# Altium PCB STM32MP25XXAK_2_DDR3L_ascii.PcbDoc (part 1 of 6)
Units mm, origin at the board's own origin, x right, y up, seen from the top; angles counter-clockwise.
Board outline 120 x 79.6 mm, 4 copper layers (Top Layer, Signal Layer 1, Signal Layer 2, Bottom Layer), stack 1.614 mm thick; 247 components, 155 nets, 1312 pads, 792 vias.
Unrouted connection lines stored in the file: 6.
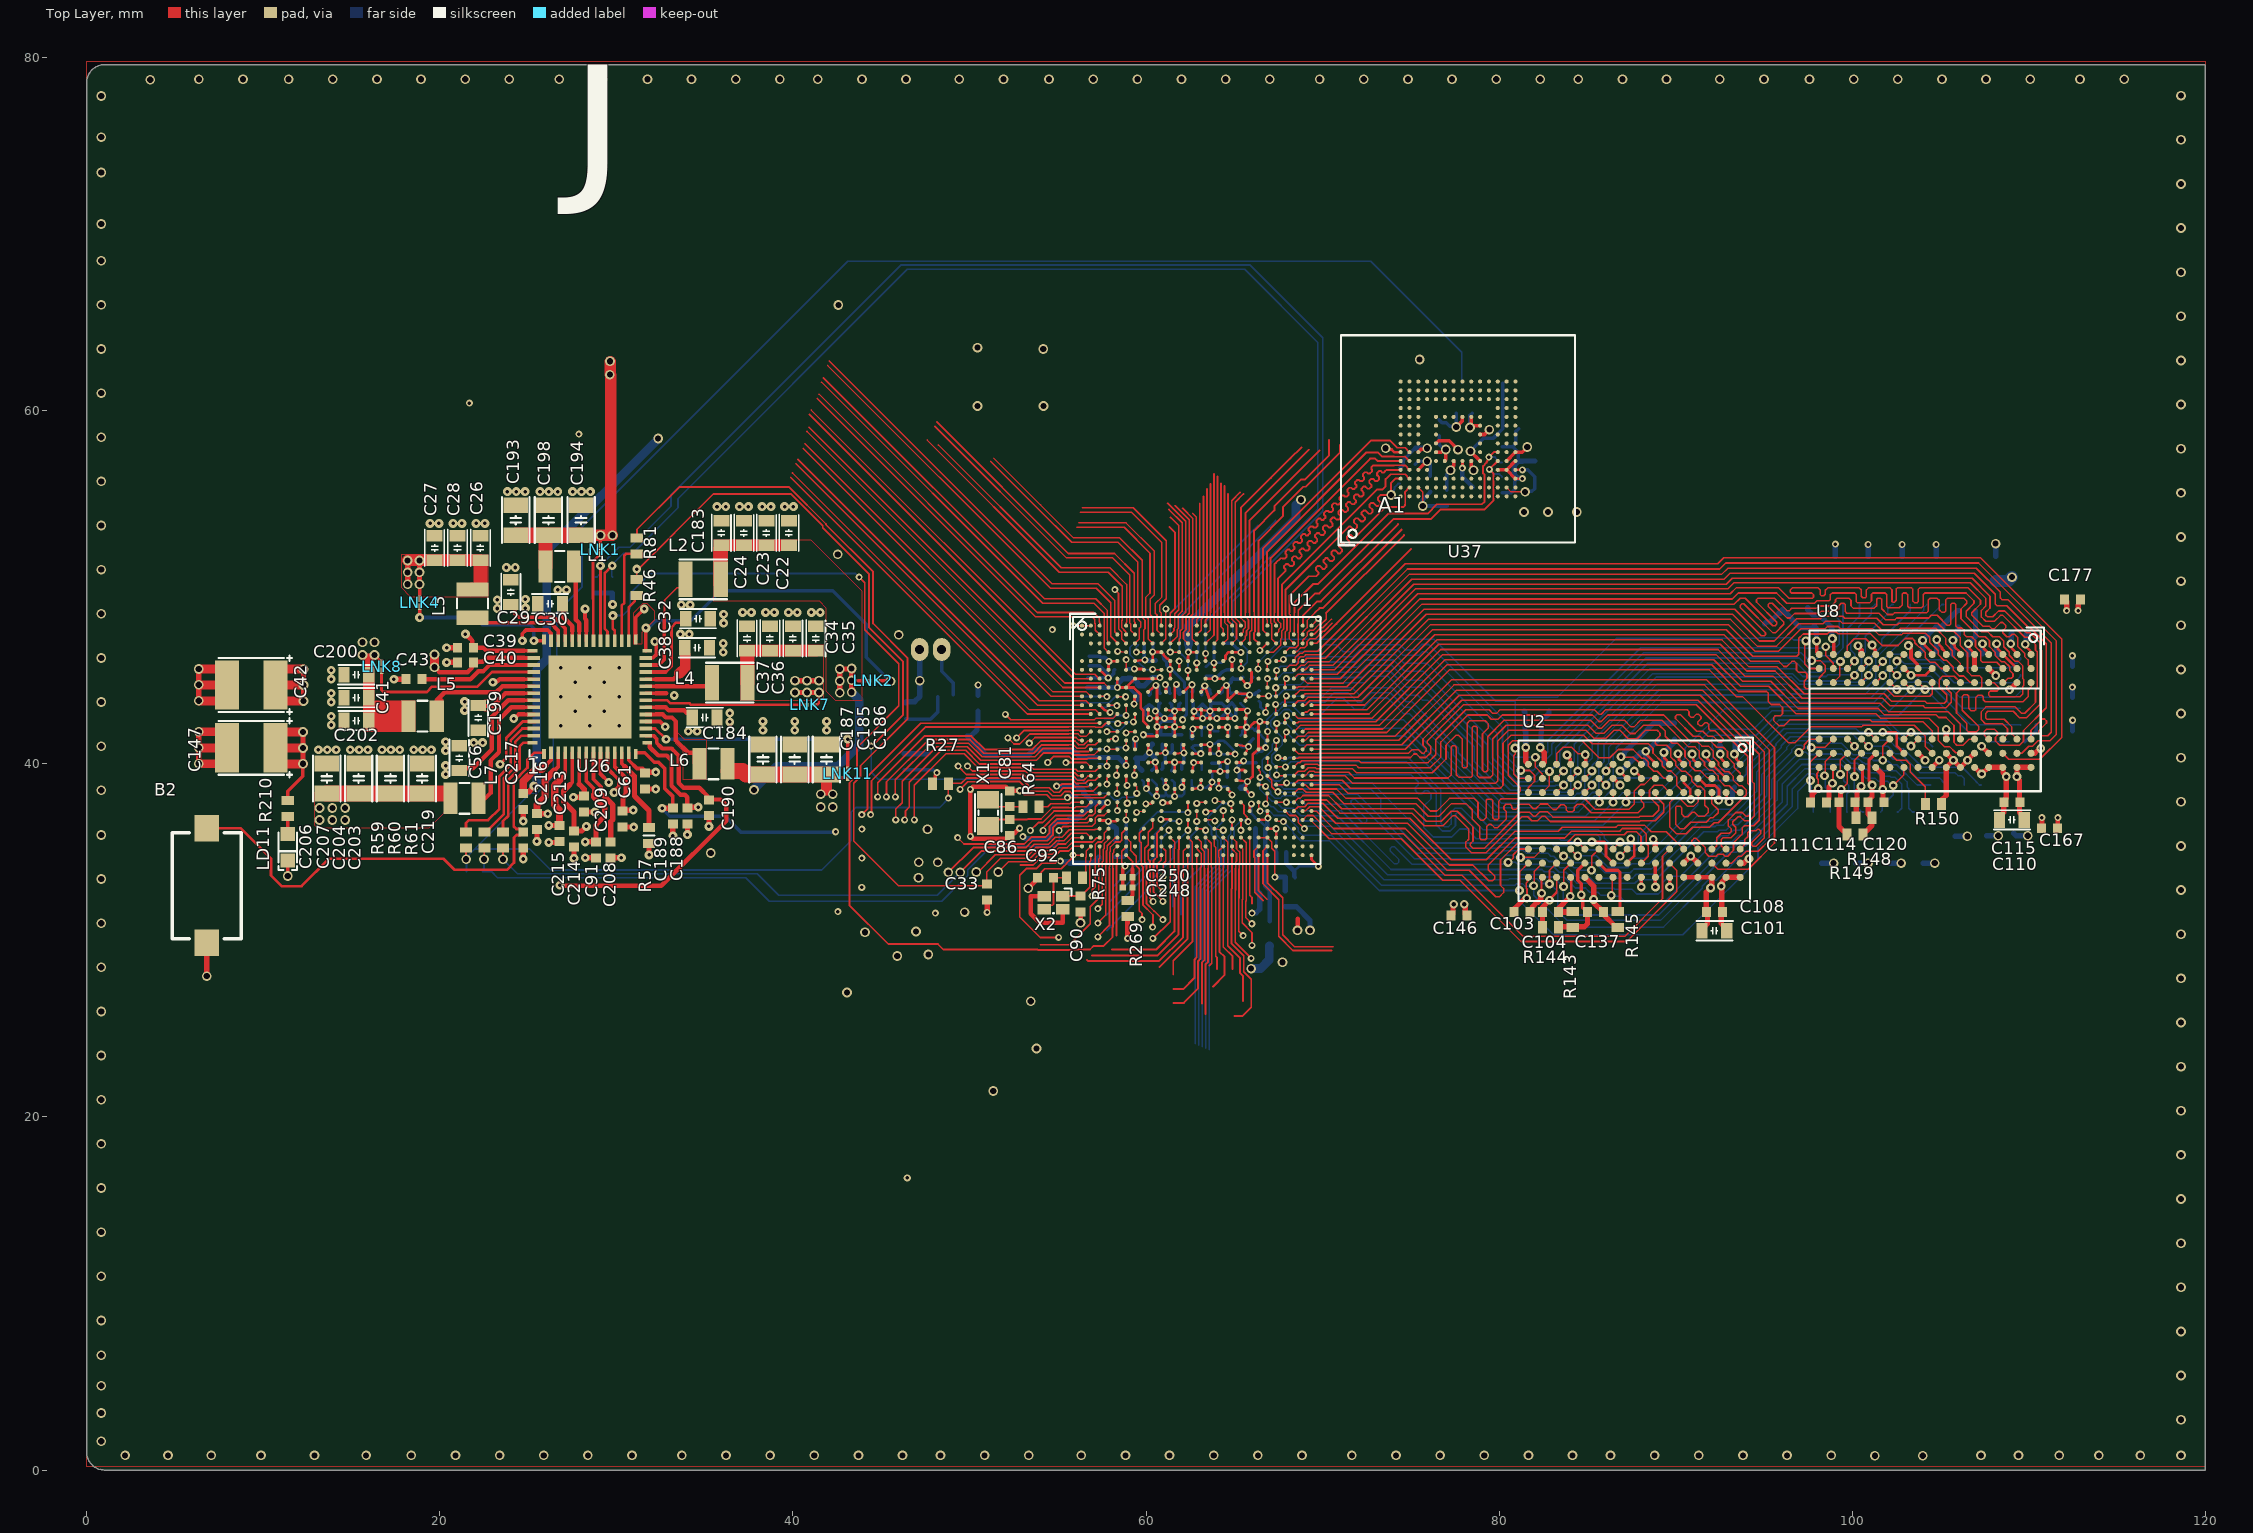
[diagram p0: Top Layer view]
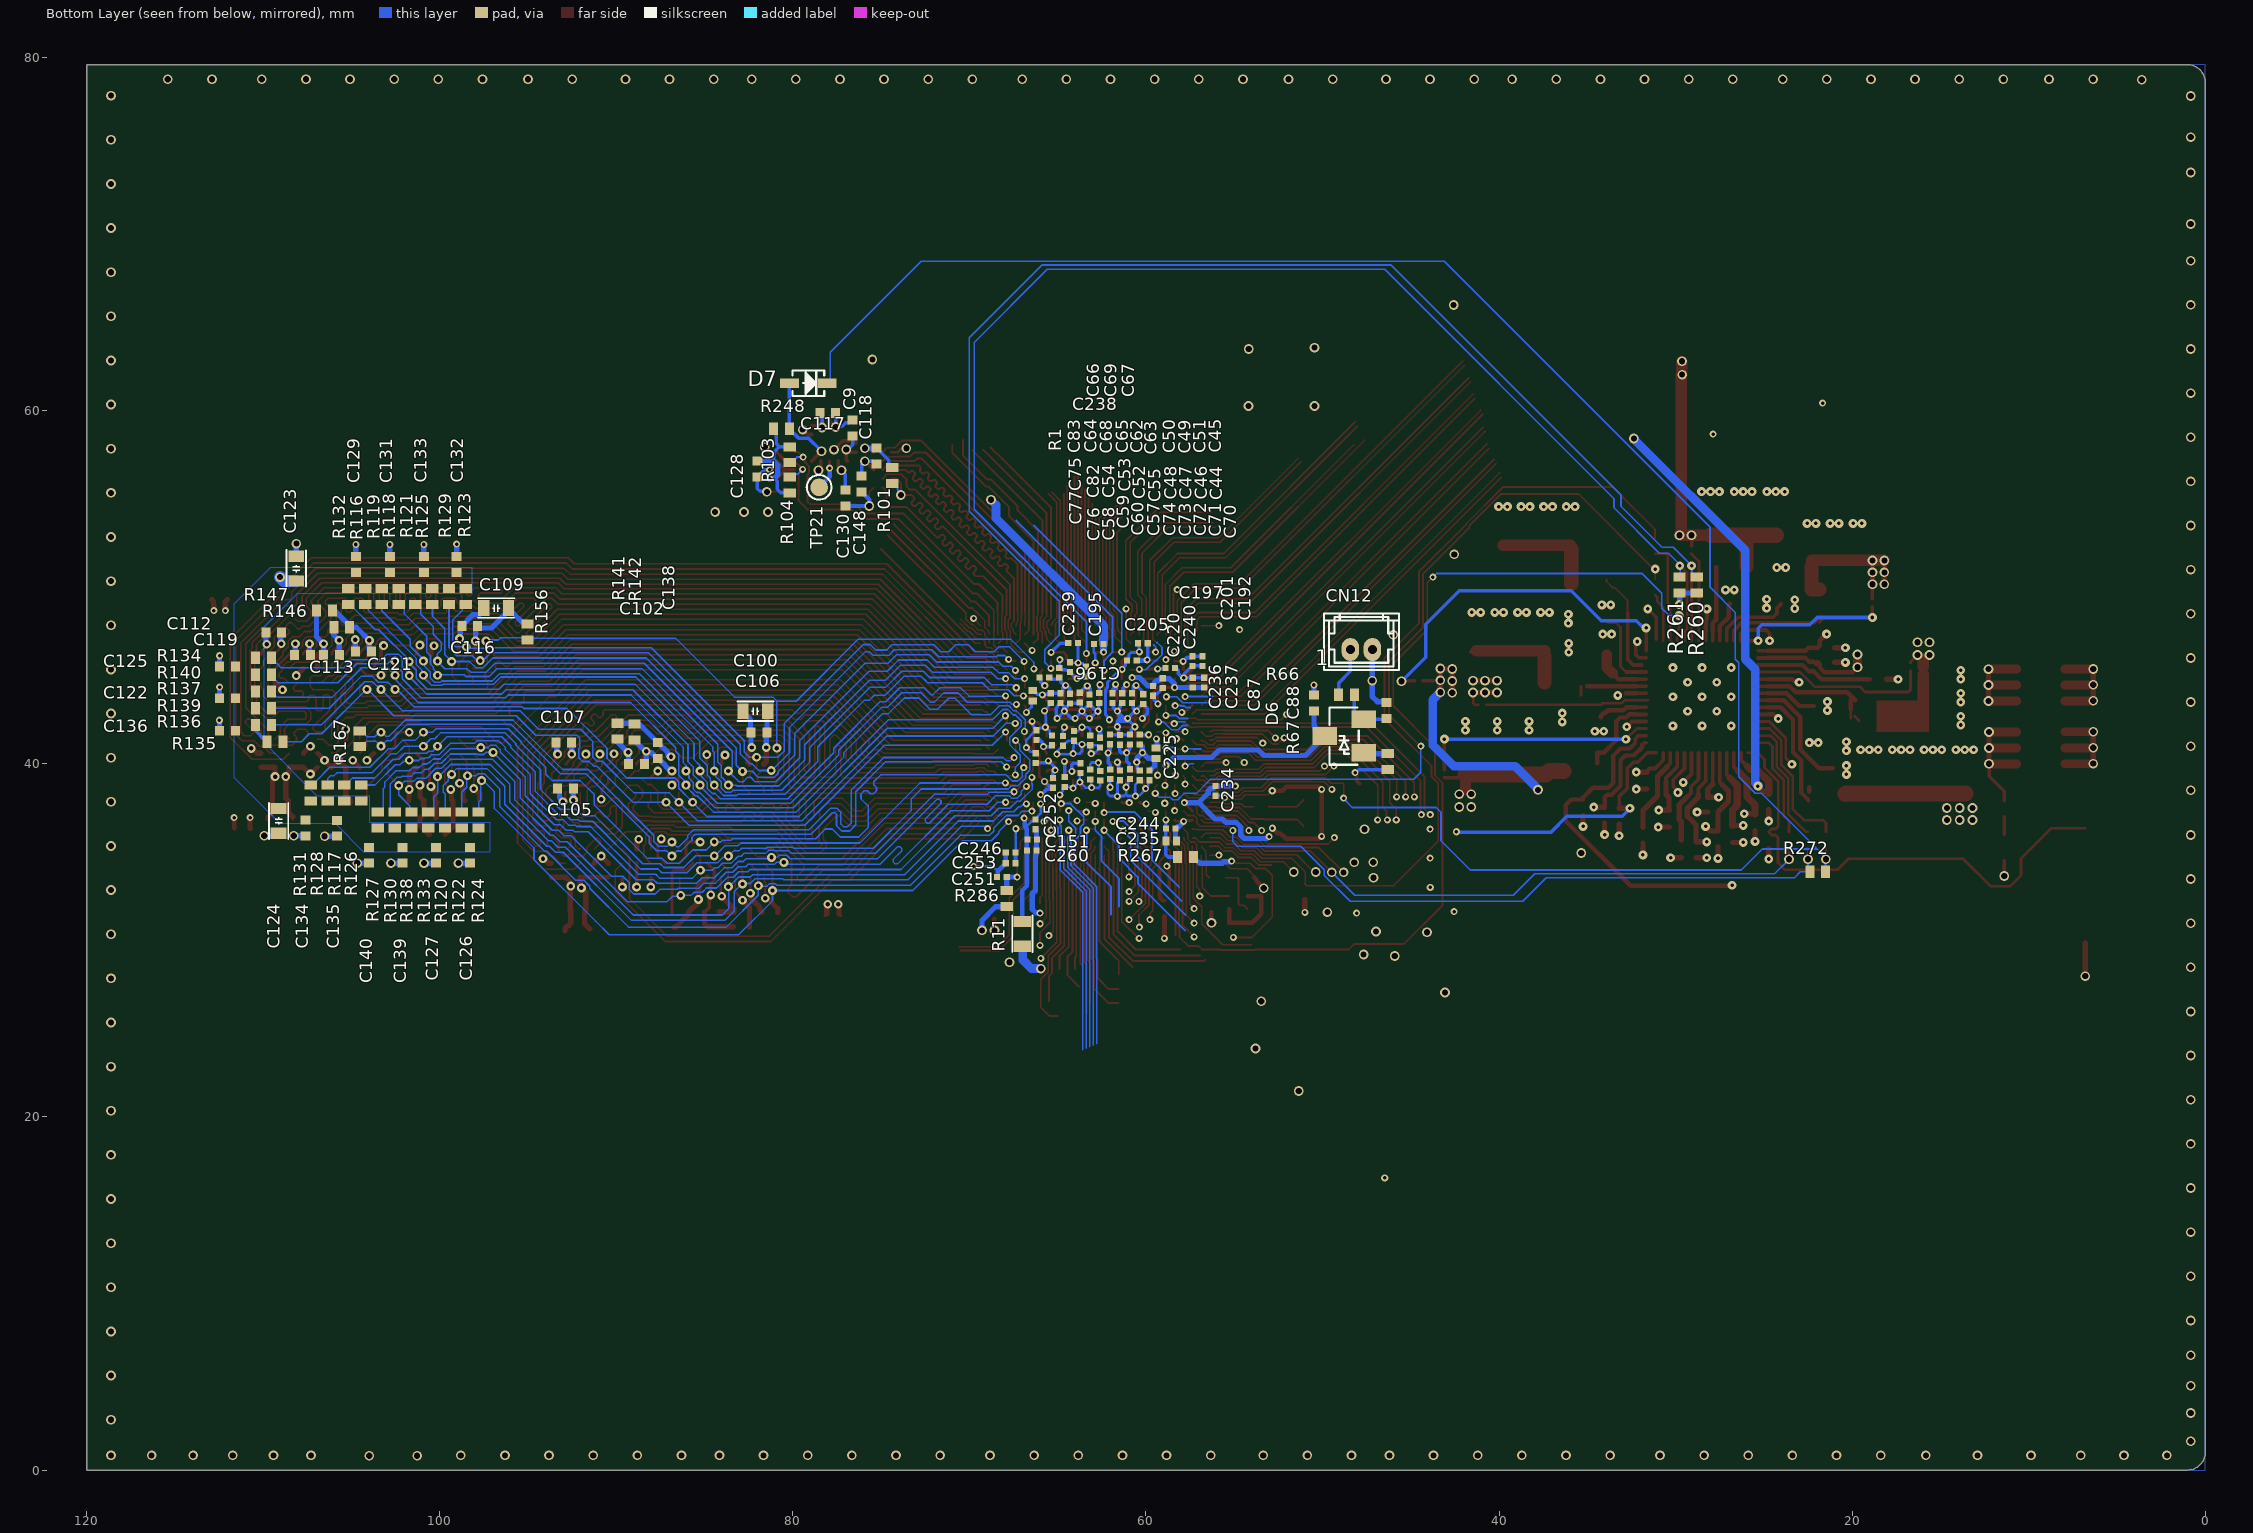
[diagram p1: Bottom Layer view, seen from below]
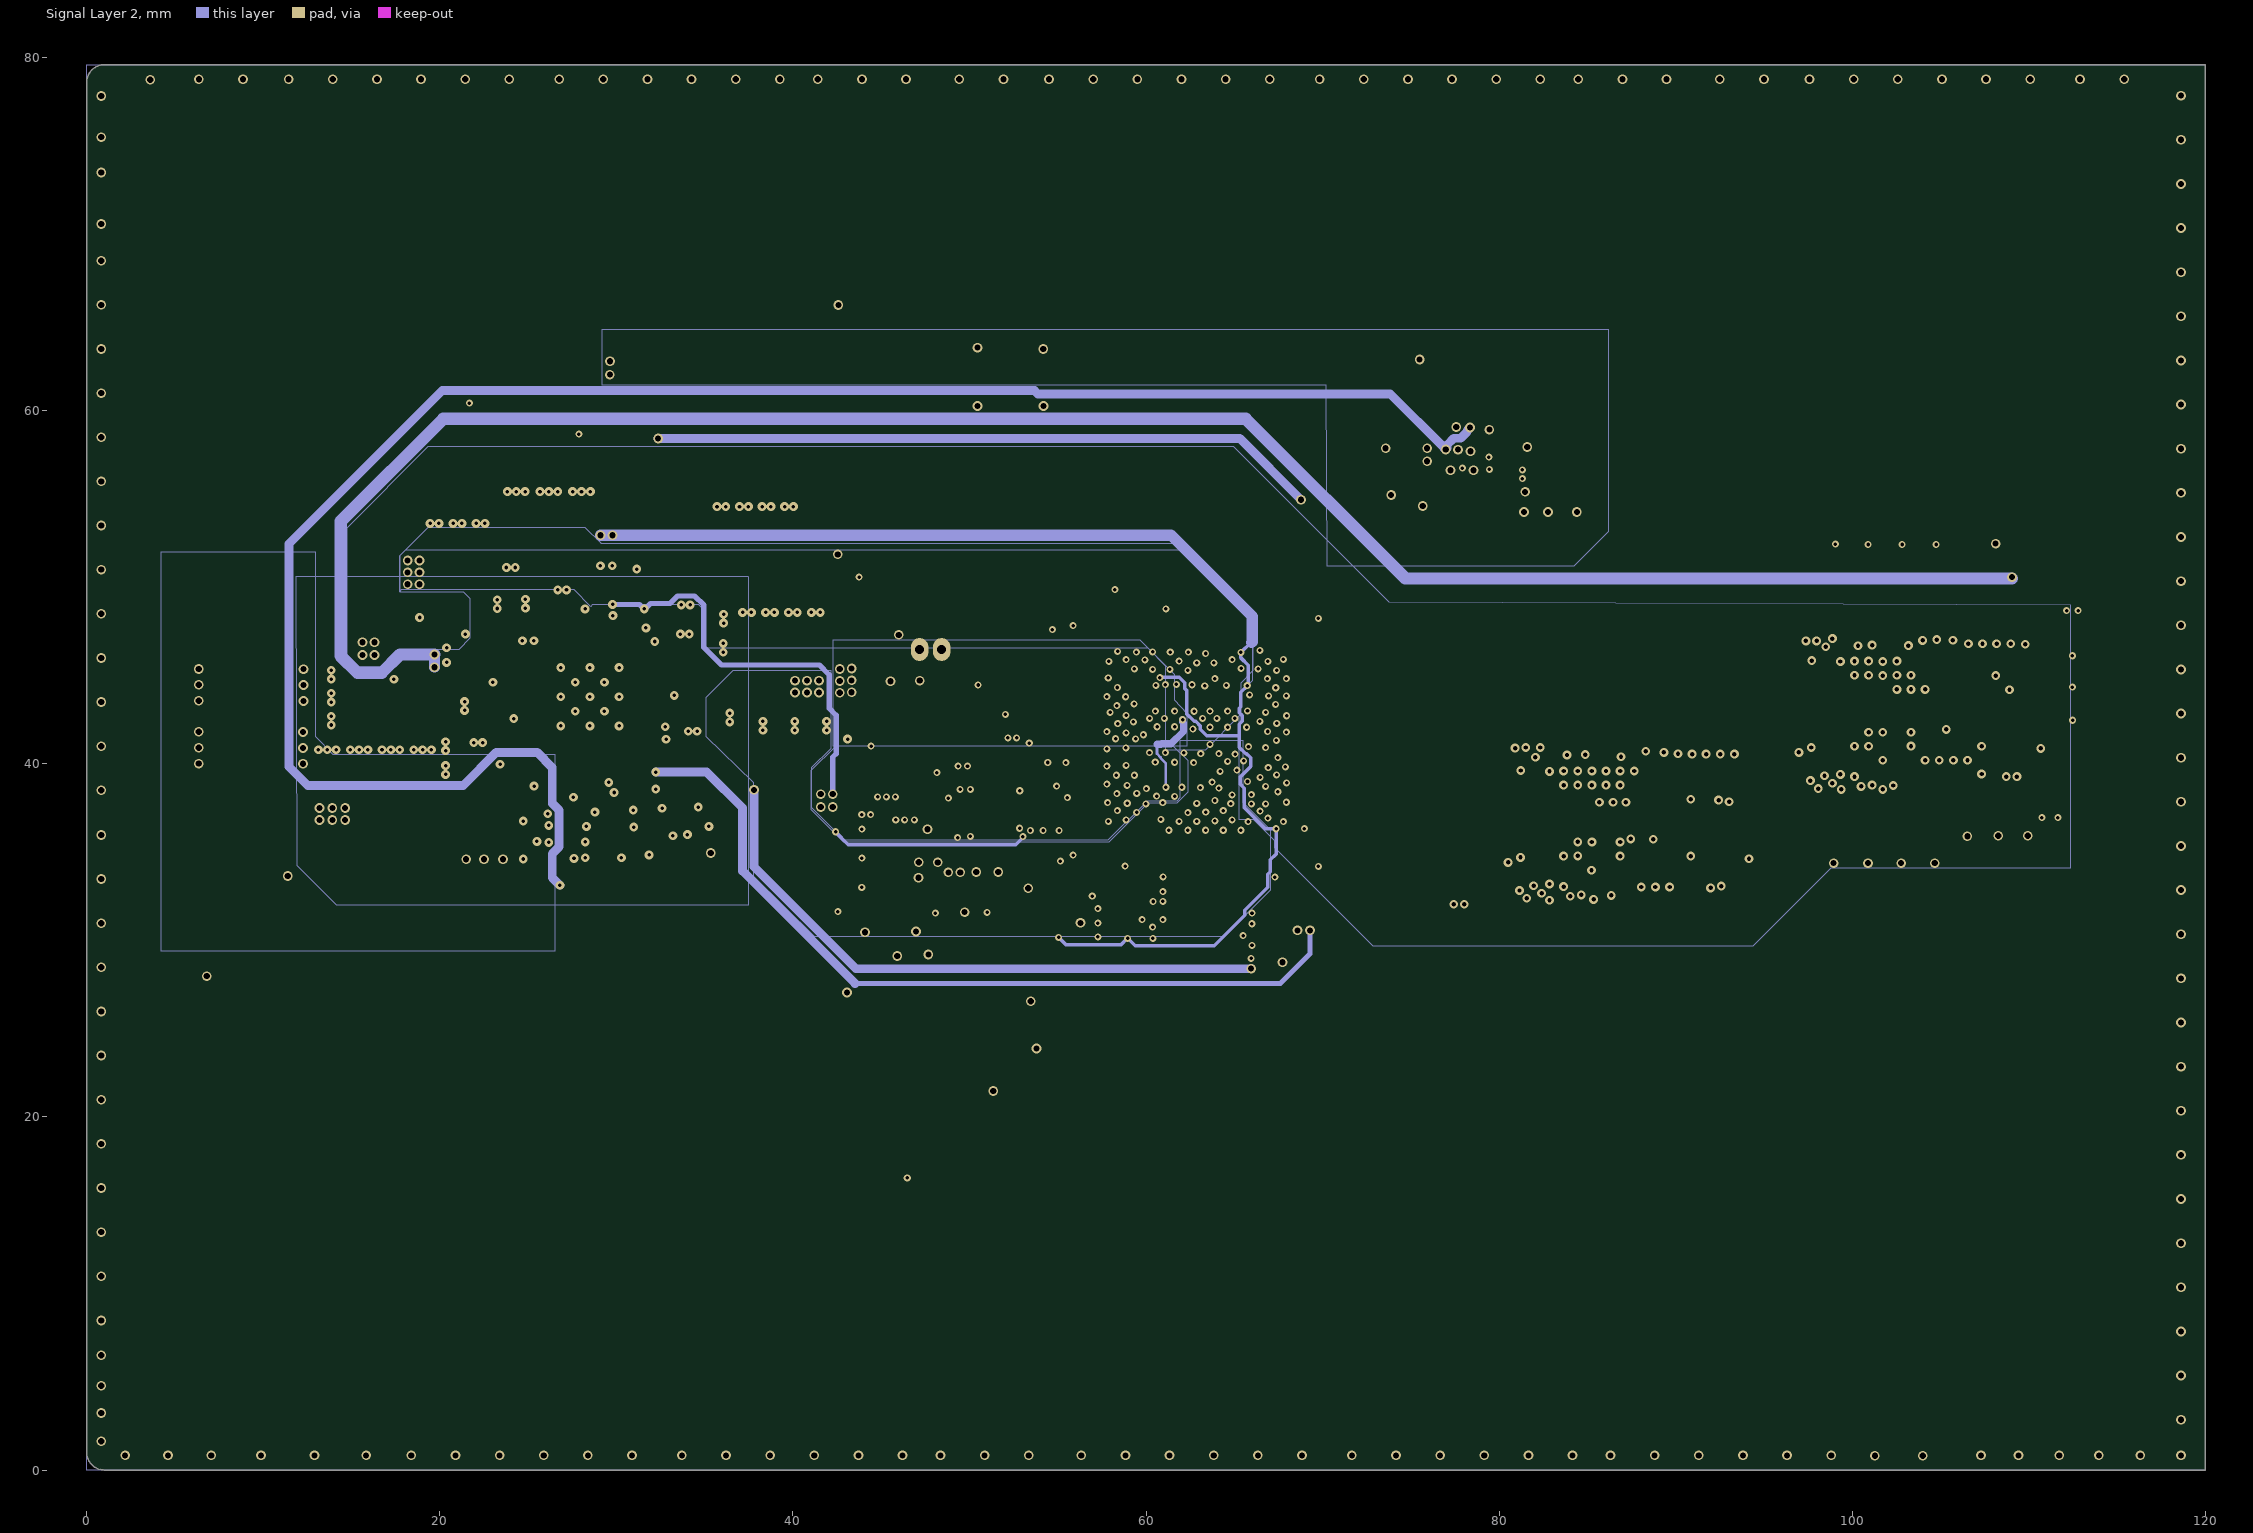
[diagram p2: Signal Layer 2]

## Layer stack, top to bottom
Top Solder: solder mask 0.025, Solder Resist, Dk 3.5
Top Layer: signal copper 0.037
Dielectric 1: prepreg 0.07, Dk 3.8
Signal Layer 1: signal copper 0.035
Dielectric 2: core 1.33, Dk 4.3
Signal Layer 2: signal copper 0.035
Dielectric 3: prepreg 0.07, Dk 3.8
Bottom Layer: signal copper 0.037
Bottom Solder: solder mask 0.025, Solder Resist, Dk 3.5

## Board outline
0,1 0,78.6 cw(c1,78.6) 1,79.6 120,79.6 120,0 1,0 cw(c1,1)

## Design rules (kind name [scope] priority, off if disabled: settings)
AssemblyTestPointUsage [All] p0: scope1count=1 scope1_0_kind=Board scope1_0_value=Board scope2count=1 scope2_0_kind=Board scope2_0_value=Board commentlength=0
AssemblyTestpoint [All] p0: scope1count=1 scope1_0_kind=Board scope1_0_value=Board scope2count=1 scope2_0_kind=Board scope2_0_value=Board commentlength=0
BoardOutlineClearance [All] p0: scope1count=1 scope1_0_kind=Board scope1_0_value=Board scope2count=1 scope2_0_kind=Board scope2_0_value=Board commentlength=0 gap=0.5
BoardOutlineClearance Silkscreen [All] p0 off: scope1count=1 scope1_0_kind=Board scope1_0_value=Board scope2count=1 scope2_0_kind=Board scope2_0_value=Board commentlength=90 gap=0 // Protel DXP Scope 1 Expression Was: OnLayer('Top Overlay') or OnLayer('Bottom Overlay')
BoardOutlineClearance Silkscreen [OnLayer('Top Overlay') or OnLayer('Bottom Overlay')] p1: gap=0 ignorepadtopadclearanceinfootprint=FALSE
BoardOutlineClearance [All] p2: gap=0.5 ignorepadtopadclearanceinfootprint=FALSE
Clearance Clearance_Default [All] p0: scope1count=1 scope1_0_kind=Board scope1_0_value=Board scope2count=1 scope2_0_kind=Board scope2_0_value=Board commentlength=0 gap=0.1
Clearance Clearance_Default [All] p1: gap=0.1 ignorepadtopadclearanceinfootprint=TRUE except(0: SMDPad-Hole Via-Hole; 0.09: Track-Track Track-SMDPad; 0.2: Arc-Hole Track-Hole THPad-Hole Fill-Hole Poly-Hole Region-Hole Text-Hole)
ComponentClearance [All] p0: scope1count=1 scope1_0_kind=Board scope1_0_value=Board scope2count=1 scope2_0_kind=Board scope2_0_value=Board commentlength=0 gap=0.2 collisioncheckmode=3
ComponentClearance [All] p1: gap=0.2 collisioncheckmode=3 verticalgap=0 showdistances=FALSE
DiffPairsRouting 100H [All] p0 off: scope1count=1 scope1_0_kind=Board scope1_0_value=Board scope2count=1 scope2_0_kind=Board scope2_0_value=Board commentlength=70 // Protel DXP Scope 1 Expression Was: InDifferentialPairClass('100H')
DiffPairsRouting 100H [InDifferentialPairClass('100H')] p1: maxlimit=0.254 minlimit=0.16 mostfreqgap=0.16 toplayer_maxgap=0.16 toplayer_minwidth=0.09 toplayer_maxwidth=0.09 toplayer_prefwidth=0.09 midlayer1_minwidth=0.09 midlayer1_maxwidth=0.381 midlayer1_prefwidth=0.09 midlayer4_minwidth=0.09 midlayer4_maxwidth=0.381 midlayer4_prefwidth=0.09 bottomlayer_maxgap=0.16 bottomlayer_minwidth=0.09 bottomlayer_maxwidth=0.09 bottomlayer_prefwidth=0.09 impedanceprofiledriven=TRUE impedanceprofileid={628B3294-B84C-4222-8D8D-B3EA8745C43E} impedanceprofilevalue=100.000000 maxuncoupledlength=12.7
FabricationTestPointUsage [All] p0: scope1count=1 scope1_0_kind=Board scope1_0_value=Board scope2count=1 scope2_0_kind=Board scope2_0_value=Board commentlength=0 valid=0 allowmultiple=FALSE
FabricationTestpoint [All] p0: scope1count=1 scope1_0_kind=Board scope1_0_value=Board scope2count=1 scope2_0_kind=Board scope2_0_value=Board commentlength=0 side=3 testpointundercomponent=TRUE minsize=1.016 maxsize=2.54 preferedsize=1.524 minholesize=0 maxholesize=1.016 preferedholesize=0.813 testpointgrid=0.025
FanoutControl Fanout_Default [All] p0: scope1count=1 scope1_0_kind=Board scope1_0_value=Board scope2count=1 scope2_0_kind=Board scope2_0_value=Board commentlength=30 // Fanout_Default (Default Rule)
FanoutControl Fanout_Small [All] p0 off: scope1count=1 scope1_0_kind=Board scope1_0_value=Board scope2count=1 scope2_0_kind=Board scope2_0_value=Board commentlength=84 // Protel DXP Scope 1 Expression Was: (CompPinCount < 5)   Fanout_Small (Default Rule)
FanoutControl Fanout_SOIC [All] p0 off: scope1count=1 scope1_0_kind=Board scope1_0_value=Board scope2count=1 scope2_0_kind=Board scope2_0_value=Board commentlength=71 // Protel DXP Scope 1 Expression Was: IsSOIC   Fanout_SOIC (Default Rule)
FanoutControl Fanout_LCC [All] p0 off: scope1count=1 scope1_0_kind=Board scope1_0_value=Board scope2count=1 scope2_0_kind=Board scope2_0_value=Board commentlength=69 // Protel DXP Scope 1 Expression Was: IsLCC   Fanout_LCC (Default Rule)
FanoutControl Fanout_BGA [All] p0 off: scope1count=1 scope1_0_kind=Board scope1_0_value=Board scope2count=1 scope2_0_kind=Board scope2_0_value=Board commentlength=69 // Protel DXP Scope 1 Expression Was: IsBGA   Fanout_BGA (Default Rule)
FanoutControl Fanout_BGA [IsBGA] p1: bgadir=Out bgaviamode=Closest fanoutstyle=Auto fanoutdirection=Alternating viagrid=0.025 // Fanout_BGA (Default Rule)
FanoutControl Fanout_LCC [IsLCC] p2: bgadir=Out bgaviamode=Closest fanoutstyle=Auto fanoutdirection=Alternating viagrid=0.025 // Fanout_LCC (Default Rule)
FanoutControl Fanout_SOIC [IsSOIC] p3: bgadir=Out bgaviamode=Closest fanoutstyle=Auto fanoutdirection=Alternating viagrid=0.025 // Fanout_SOIC (Default Rule)
FanoutControl Fanout_Small [(CompPinCount < 5)] p4: bgadir=Out bgaviamode=Closest fanoutstyle=Auto fanoutdirection=OutThenIn viagrid=0.025 // Fanout_Small (Default Rule)
FanoutControl Fanout_Default [All] p5: bgadir=Out bgaviamode=Closest fanoutstyle=Auto fanoutdirection=Alternating viagrid=0.025 // Fanout_Default (Default Rule)
Height [All] p0: scope1count=1 scope1_0_kind=Board scope1_0_value=Board scope2count=1 scope2_0_kind=Board scope2_0_value=Board commentlength=0
HoleSize [All] p0: scope1count=1 scope1_0_kind=Board scope1_0_value=Board scope2count=1 scope2_0_kind=Board scope2_0_value=Board commentlength=0 absolutevalues=TRUE maxlimit=10 minlimit=0.1 maxpercent=80.000 minpercent=20.000
HoleSize [All] p1: absolutevalues=TRUE maxlimit=10 minlimit=0.1 maxpercent=80.000 minpercent=20.000
HoleToHoleClearance [All] p0: scope1count=1 scope1_0_kind=Board scope1_0_value=Board scope2count=1 scope2_0_kind=Board scope2_0_value=Board commentlength=0
HoleToHoleClearance [All] p1: gap=0.25 allowstackedmicrovias=TRUE
LayerPairs [All] p0: scope1count=1 scope1_0_kind=Board scope1_0_value=Board scope2count=1 scope2_0_kind=Board scope2_0_value=Board commentlength=0 enforce=TRUE
MinimumSolderMaskSliver MinimumSolderMaskSliver_SOLDER_BRIDGE [All] p0: scope1count=1 scope1_0_kind=Board scope1_0_value=Board scope2count=1 scope2_0_kind=Footprint scope2_0_value=SOLDER-BRIDGE_R0603-0R commentlength=0
MinimumSolderMaskSliver [All] p0: scope1count=1 scope1_0_kind=Board scope1_0_value=Board scope2count=1 scope2_0_kind=Board scope2_0_value=Board commentlength=0
MinimumSolderMaskSliver MinimumSolderMaskSliver_SOLDER_BRIDGE [All vs HasFootprint('SOLDER-BRIDGE_R0603-0R')] p1: minsoldermaskwidth=0.07
MinimumSolderMaskSliver [All] p2: minsoldermaskwidth=0.075
NetAntennae [All] p0 off: scope1count=1 scope1_0_kind=Board scope1_0_value=Board scope2count=1 scope2_0_kind=Board scope2_0_value=Board commentlength=0
NetAntennae [All] p1 off: netantennaetolerance=0
PasteMaskExpansion [All] p0: scope1count=1 scope1_0_kind=Board scope1_0_value=Board scope2count=1 scope2_0_kind=Board scope2_0_value=Board commentlength=0 expansion=0
PlaneClearance [All] p0: scope1count=1 scope1_0_kind=Board scope1_0_value=Board scope2count=1 scope2_0_kind=Board scope2_0_value=Board commentlength=0 clearance=0.508
PlaneConnect [All] p0: scope1count=1 scope1_0_kind=Board scope1_0_value=Board scope2count=1 scope2_0_kind=Board scope2_0_value=Board commentlength=0 planeconnectstyle=Direct reliefexpansion=0.508 reliefentries=4 reliefconductorwidth=0.21 reliefairgap=0.21
PlaneConnect [All] p1: planeconnectstyle=Direct reliefexpansion=0.508 reliefentries=4 reliefconductorwidth=0.21 reliefairgap=0.21
PolygonConnect PolygonConnect_Default [All] p0: scope1count=1 scope1_0_kind=Board scope1_0_value=Board scope2count=1 scope2_0_kind=Board scope2_0_value=Board commentlength=0 connectstyle=Direct reliefconductorwidth=0.25 reliefentries=4 polygonreliefangle="90 Angle"
PolygonConnect PolygonConnect_Default [All] p1: connectstyle=Direct reliefconductorwidth=0.25 reliefentries=4 polygonreliefangle="90 Angle" airgapwidth=0.25
RoomDefinition RoomDefinition_eMMC [All] p0 off: scope1count=1 scope1_0_kind=Board scope1_0_value=Board scope2count=1 scope2_0_kind=Board scope2_0_value=Board commentlength=44 region_x1=366825123 region_y1=339606300 region_x2=369695387 region_y2=342521149 confinementstyle=ConfineIn // Protel DXP Scope 1 Expression Was: False
RoomDefinition RoomDefinition_DDR [All] p0 off: scope1count=1 scope1_0_kind=Board scope1_0_value=Board scope2count=1 scope2_0_kind=Board scope2_0_value=Board commentlength=44 region_x1=368782677 region_y1=331242320 region_x2=373417322 region_y2=337462792 confinementstyle=ConfineIn // Protel DXP Scope 1 Expression Was: False
RoomDefinition U_PMIC [All] p0: scope1count=1 scope1_0_kind=ComponentClass scope1_0_value=U_PMIC scope2count=1 scope2_0_kind=Board scope2_0_value=Board commentlength=0 region_x1=359568897 region_y1=331484252 region_x2=365277559 region_y2=337192914 confinementstyle=ConfineIn
RoomDefinition RoomDefinition_eMMC [False] p1: confinementstyle=ConfineIn formatcopy=TRUE lockcomponents=FALSE outline 74.056,62.109 81.346,62.109 81.346,54.705 74.056,54.705
RoomDefinition RoomDefinition_DDR [False] p2: confinementstyle=ConfineIn formatcopy=TRUE lockcomponents=FALSE outline 79.028,49.26 90.8,49.26 90.8,33.46 79.028,33.46
RoomDefinition U_PMIC [InComponentClass('U_PMIC')] p3: confinementstyle=ConfineIn formatcopy=TRUE lockcomponents=FALSE outline 55.625,48.575 70.125,48.575 70.125,34.075 55.625,34.075
RoutingCorners [All] p0: scope1count=1 scope1_0_kind=Board scope1_0_value=Board scope2count=1 scope2_0_kind=Board scope2_0_value=Board commentlength=0 cornerstyle=45-Degree minsetback=2.54 maxsetback=2.54
RoutingLayers [All] p0: scope1count=1 scope1_0_kind=Board scope1_0_value=Board scope2count=1 scope2_0_kind=Board scope2_0_value=Board commentlength=0 top layer=Automatic mid layer 1=Automatic mid layer 4=Automatic bottom layer=Automatic
RoutingPriority [All] p0: scope1count=1 scope1_0_kind=Board scope1_0_value=Board scope2count=1 scope2_0_kind=Board scope2_0_value=Board commentlength=0
RoutingTopology [All] p0: scope1count=1 scope1_0_kind=Board scope1_0_value=Board scope2count=1 scope2_0_kind=Board scope2_0_value=Board commentlength=0 topology=Shortest
RoutingVias RoutingVias_Default [All] p0 off: scope1count=1 scope1_0_kind=Board scope1_0_value=Board scope2count=1 scope2_0_kind=Board scope2_0_value=Board commentlength=83 holewidth=0.15 width=0.4 viastyle="Through Hole" minholewidth=0.15 minwidth=0.4 maxholewidth=0.35 maxwidth=0.6 // Protel DXP Scope 1 Expression Was: InDrillLayerPair('Top Layer - Bottom Layer')
RoutingVias RoutingVias_Default [InDrillLayerPair('Top Layer - Bottom Layer')] p1: holewidth=0.15 width=0.4 viastyle="Through Hole" minholewidth=0.15 minwidth=0.4 maxholewidth=0.35 maxwidth=0.6 useviatemplates=TRUE viatemplateguid#1={8082EAB8-D593-4669-9C8E-234CD125C595} viatemplateguid#2={0C56A9B8-CF93-463B-97D5-BDCC265789B0} viatemplateguid#3={EB48A735-9776-404B-ACA6-A88A516247F0} viatemplateguid#4={9F28DA9E-6088-4B56-A5CF-E6C86A3E97F7} viatemplatename#1=v40h20m0mx0 viatemplatename#2=v50h20m25 viatemplatename#3=v50h25m30 viatemplatename#4=v55h35m40mx40
ShortCircuit [All] p0 off: scope1count=1 scope1_0_kind=Board scope1_0_value=Board scope2count=1 scope2_0_kind=Board scope2_0_value=Board commentlength=0 allowed=FALSE
ShortCircuit [All] p1 off: allowed=FALSE
SilkToBoardRegionClearance [All] p0: scope1count=1 scope1_0_kind=Board scope1_0_value=Board scope2count=1 scope2_0_kind=Board scope2_0_value=Board commentlength=0
SilkToSilkClearance [All] p0: scope1count=1 scope1_0_kind=Board scope1_0_value=Board scope2count=1 scope2_0_kind=Board scope2_0_value=Board commentlength=0
SilkToSilkClearance [All] p1: silktosilkclearance=0.2
SilkToSolderMaskClearance [All] p0 off: scope1count=1 scope1_0_kind=Board scope1_0_value=Board scope2count=1 scope2_0_kind=Board scope2_0_value=Board commentlength=44 // Protel DXP Scope 1 Expression Was: IsPad
SilkToSolderMaskClearance [IsPad] p1: minsilkscreentomaskgap=0.015 clearancetoexposedcopper=TRUE
SolderMaskExpansion [All] p0: scope1count=1 scope1_0_kind=Board scope1_0_value=Board scope2count=1 scope2_0_kind=Board scope2_0_value=Board commentlength=0 expansion=0.1
SolderMaskExpansion [All] p1: expansion=0.1 istentingtop=FALSE
UnRoutedNet [All] p0 off: scope1count=1 scope1_0_kind=Board scope1_0_value=Board scope2count=1 scope2_0_kind=Board scope2_0_value=Board commentlength=0
UnRoutedNet [All] p1 off:
UnpouredPolygon [All] p0: scope1count=1 scope1_0_kind=Board scope1_0_value=Board scope2count=1 scope2_0_kind=Board scope2_0_value=Board commentlength=0
ViasUnderSMD [All] p0: scope1count=1 scope1_0_kind=PadClass scope1_0_value=PC_VIAS-IN-PAD_OK scope2count=1 scope2_0_kind=Board scope2_0_value=Board commentlength=0 allowed=TRUE
ViasUnderSMD [InPadClass('PC_VIAS-IN-PAD_OK')] p1: allowed=TRUE
Width Width_Default [All] p0: scope1count=1 scope1_0_kind=Net scope1_0_value=GND scope2count=1 scope2_0_kind=Board scope2_0_value=Board commentlength=0 maxlimit=10 minlimit=0.09 preferedwidth=0.3
Width Width_SINGLE_DDR_55R [All] p0: scope1count=1 scope1_0_kind=NetClass scope1_0_value=55H scope2count=1 scope2_0_kind=Board scope2_0_value=Board commentlength=0 maxlimit=0.199 minlimit=0.078 preferedwidth=0.199
Width Width_SINGLE_50R [All] p0: scope1count=1 scope1_0_kind=NetClass scope1_0_value=50H scope2count=1 scope2_0_kind=Board scope2_0_value=Board commentlength=0 maxlimit=0.199 minlimit=0.078 preferedwidth=0.199
Width Width_SINGLE_50R [InNetClass('50H')] p1: maxlimit=0.199 minlimit=0.078 preferedwidth=0.199 toplayer_minwidth=0.09 toplayer_maxwidth=0.11 toplayer_prefwidth=0.11 bottomlayer_minwidth=0.11 bottomlayer_maxwidth=0.11 bottomlayer_prefwidth=0.11 impedanceprofiledriven=TRUE impedanceprofileid={152E730A-FDA4-4006-BF82-0EE0D5C1A339} impedanceprofilevalue=50.000000 minimp=50.000000 maximp=50.000000 favimp=50.000000
Width Width_SINGLE_DDR_55R [InNetClass('55H')] p2: maxlimit=0.199 minlimit=0.078 preferedwidth=0.199 toplayer_minwidth=0.09 toplayer_maxwidth=0.09 toplayer_prefwidth=0.09 bottomlayer_minwidth=0.09 bottomlayer_maxwidth=0.09 bottomlayer_prefwidth=0.09 impedanceprofiledriven=TRUE impedanceprofileid={D5948A69-504E-4D29-B9E5-77B49DDD78E4} impedanceprofilevalue=55.000000 minimp=50.000000 maximp=50.000000 favimp=50.000000
Width Width_Default [InNet('GND')] p3: maxlimit=10 minlimit=0.09 preferedwidth=0.3
14 further rules are at their usual default settings.

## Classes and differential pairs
net class 100H: DDR_CLK_N DDR_CLK_P DDR_DQS0_N DDR_DQS0_P DDR_DQS1_N DDR_DQS1_P DDR_DQS2_N DDR_DQS2_P DDR_DQS3_N DDR_DQS3_P
net class 55H: DDR_A0 DDR_A1 DDR_A2 DDR_A3 DDR_A4 DDR_A5 DDR_A6 DDR_A7 DDR_A8 DDR_A9 DDR_A10 DDR_A11 DDR_A12 DDR_A13 DDR_A14 DDR_A15 DDR_BA0 DDR_BA1 DDR_BA2 DDR_CASN DDR_CKE DDR_CSN DDR_DQ0 DDR_DQ1 DDR_DQ2 DDR_DQ3 DDR_DQ4 DDR_DQ5 DDR_DQ6 DDR_DQ7 DDR_DQ8 DDR_DQ9 DDR_DQ10 DDR_DQ11 DDR_DQ12 DDR_DQ13 DDR_DQ14 DDR_DQ15 DDR_DQ16 DDR_DQ17 DDR_DQ18 DDR_DQ19 DDR_DQ20 DDR_DQ21 DDR_DQ22 DDR_DQ23 DDR_DQ24 DDR_DQ25 DDR_DQ26 DDR_DQ27 DDR_DQ28 DDR_DQ29 DDR_DQ30 DDR_DQ31 DDR_DQM0 DDR_DQM1 DDR_DQM2 DDR_DQM3 DDR_ODT DDR_RASN DDR_RESETN DDR_WEN
net class eMMC.SDMMC2_D[0..7]: eMMC.SDMMC2_CK eMMC.SDMMC2_CMD eMMC.SDMMC2_D0 eMMC.SDMMC2_D1 eMMC.SDMMC2_D2 eMMC.SDMMC2_D3 eMMC.SDMMC2_D4 eMMC.SDMMC2_D5 eMMC.SDMMC2_D6 eMMC.SDMMC2_D7
component class U_eMMC: C9 C117 C118 C128 C130 C148 D7 R101 R103 R104 R248 TP21 U37
component class "U_STM32MP25XXAK I_Os": C33 C81 C86 C90 C92 R27 R64 R75 R260 R261 R272 U1 X1 X2
component class U_2_DDR3L_16bits: C100 C101 C102 C103 C104 C105 C106 C107 C108 C109 C110 C111 C112 C113 C114 C115 C116 C119 C120 C121 C122 C123 C124 C125 C126 C127 C129 C131 C132 C133 C134 C135 C136 C137 C138 C139 C140 C146 C167 C177 R1 R116 R117 R118 R119 R120 R121 R122 R123 R124 R125 R126 R127 R128 R129 R130 R131 R132 R133 R134 R135 R136 R137 R138 R139 R140 R141 R142 R143 R144 R145 R146 R147 R148 R149 R150 R156 R167 U2 U8
component class "U_STM32MP25XXAK Power": C44 C45 C46 C47 C48 C49 C50 C51 C52 C53 C54 C55 C57 C58 C59 C60 C62 C63 C64 C65 C66 C67 C68 C69 C70 C71 C72 C73 C74 C75 C76 C77 C82 C83 C87 C88 C151 C192 C195 C196 C197 C201 C205 C220 C225 C234 C235 C236 C237 C238 C239 C240 C244 C246 C248 C250 C251 C252 C253 C260 CN12 D6 R11 R66 R67 R267 R269 R286
component class U_PMIC: B2 C22 C23 C24 C26 C27 C28 C29 C30 C32 C34 C35 C36 C37 C38 C39 C40 C41 C42 C43 C56 C61 C91 C147 C183 C184 C185 C186 C187 C188 C189 C190 C193 C194 C198 C199 C200 C202 C203 C204 C206 C207 C208 C209 C213 C214 C215 C216 C217 C219 L1 L2 L3 L4 L5 L6 L7 LD11 LNK1 LNK2 LNK4 LNK7 LNK8 LNK11 R46 R57 R59 R60 R61 R81 R210 U26
differential pair DDR_DQS3_NP: +DDR_DQS3_P -DDR_DQS3_N
differential pair DDR_DQS2_NP: +DDR_DQS2_P -DDR_DQS2_N
differential pair DDR_CLK_NP: +DDR_CLK_P -DDR_CLK_N
differential pair DDR_DQS1_NP: +DDR_DQS1_P -DDR_DQS1_N
differential pair " ": +DDR_DQS0_P -DDR_DQS0_N

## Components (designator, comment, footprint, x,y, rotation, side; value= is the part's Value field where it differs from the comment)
B2 "SW_PUSH_SMD_2P" SWI_WE_434121025816 6.795,33.104 r90 top
C9 "Capacitor" C0402 76.615,59.03 r270 bottom
C22 "Capacitor" C0603 39.775,53.075 r270 top
C23 "Capacitor" C0603 38.5,53.075 r270 top
C24 "Capacitor" C0603 37.225,53.075 r270 top
C26 "Capacitor" C0603 22.3,52.225 r270 top
C27 "Capacitor" C0603 19.7,52.225 r270 top
C28 "Capacitor" C0603 21,52.225 r270 top
C29 "Capacitor" C0603 24.025,49.725 r270 top
C30 "Capacitor" C0603 26.25,49.075 r0 top
C32 "Capacitor" C0603 34.625,48.225 r180 top
C33 "Capacitor" C0402 51,32.75 r90 top
C34 "Capacitor" C0603 40,47.1 r270 top
C35 "Capacitor" C0603 41.3,47.1 r270 top
C36 "Capacitor" C0603 38.7,47.1 r270 top
C37 "Capacitor" C0603 37.4,47.1 r270 top
C38 "Capacitor" C0603 34.575,46.575 r180 top
C39 "Capacitor" C0402 21.445,46.575 r0 top
C40 "Capacitor" C0402 21.445,45.75 r0 top
C41 "Capacitor" C0603 15.275,43.75 r0 top
C42 "Cap_POL_TANA" CPOL_TCJ-B_1210_H210 9.311,44.468 r180 top
C43 "Capacitor" C0402 18.535,44.8 r0 top
C44 "1uF" C0201_MURATA_GRM033_H0P3 60.351,41.38 r270 bottom
C45 "1uF" C0201_MURATA_GRM033_H0P3 60.16,43.67 r270 bottom
C46 "1uF" C0201_MURATA_GRM033_H0P3 60.915,41.38 r90 bottom
C47 "1uF" C0201_MURATA_GRM033_H0P3 61.476,41.356 r270 bottom
C48 "1uF" C0201_MURATA_GRM033_H0P3 62.038,41.382 r90 bottom
C49 "1uF" C0201_MURATA_GRM033_H0P3 61.35,43.725 r270 bottom
C50 "1uF" C0201_MURATA_GRM033_H0P3 61.9,43.725 r270 bottom
C51 "1uF" C0201_MURATA_GRM033_H0P3 60.8,43.725 r270 bottom
C52 "1uF" C0201_MURATA_GRM033_H0P3 63.162,41.332 r270 bottom
C53 "1uF" C0201_MURATA_GRM033_H0P3 64.083,41.581 r270 bottom
C54 "1uF" C0201_MURATA_GRM033_H0P3 64.706,41.304 r270 bottom
C55 "1uF" C0201_MURATA_GRM033_H0P3 62.6,41.2 r270 bottom
C56 "Capacitor" C0603 21.1,40.325 r270 top
C57 "1uF" C0201_MURATA_GRM033_H0P3 62.592,39.328 r270 bottom
C58 "1uF" C0201_MURATA_GRM033_H0P3 64.607,38.972 r270 bottom
C59 "1uF" C0201_MURATA_GRM033_H0P3 63.714,39.761 r270 bottom
C60 "1uF" C0201_MURATA_GRM033_H0P3 63.154,39.397 r270 bottom
C61 "Capacitor" C0402 31.625,39.02 r90 top
C62 "1uF" C0201_MURATA_GRM033_H0P3 63.2,43.65 r90 bottom
C63 "1uF" C0201_MURATA_GRM033_H0P3 62.65,43.73 r270 bottom
C64 "1uF" C0201_MURATA_GRM033_H0P3 64.85,43.725 r270 bottom
C65 "1uF" C0201_MURATA_GRM033_H0P3 63.75,43.75 r90 bottom
C66 "1uF" C0201_MURATA_GRM033_H0P3 64.915,45.16 r90 bottom
C67 "1uF" C0201_MURATA_GRM033_H0P3 63.4,45.225 r270 bottom
C68 "1uF" C0201_MURATA_GRM033_H0P3 64.3,43.7 r270 bottom
C69 "1uF" C0201_MURATA_GRM033_H0P3 64.305,45.477 r270 bottom
C70 "1uF" C0201_MURATA_GRM033_H0P3 59.805,39.35 r90 bottom
C71 "1uF" C0201_MURATA_GRM033_H0P3 60.355,39.35 r270 bottom
C72 "1uF" C0201_MURATA_GRM033_H0P3 60.905,39.423 r270 bottom
C73 "1uF" C0201_MURATA_GRM033_H0P3 61.467,39.349 r90 bottom
C74 "1uF" C0201_MURATA_GRM033_H0P3 62.03,39.408 r270 bottom
C75 "1uF" C0201_MURATA_GRM033_H0P3 66.205,41.625 r90 bottom
C76 "1uF" C0201_MURATA_GRM033_H0P3 65.274,38.923 r270 bottom
C77 "1uF" C0201_MURATA_GRM033_H0P3 66.25,40.325 r270 bottom
C81 "Capacitor" C0402 52.285,38.025 r90 top
C82 "1uF" C0201_MURATA_GRM033_H0P3 65.325,41.325 r90 bottom
C83 "1uF" C0201_MURATA_GRM033_H0P3 65.395,43.725 r270 bottom
C86 "Capacitor" C0402 52.285,36.4 r270 top
C87 "" C0402 50.485,43.438 r270 bottom
C88 "Capacitor" C0402 46.382,43.015 r270 bottom
C90 "Capacitor" C0402 56.293,32.06 r90 top
C91 "Capacitor" C0402 28.85,35.13 r270 top
C92 "Capacitor" C0402 54.309,33.546 r180 top
C100 "Capacitor" C0603 82.133,42.975 r0 bottom
C101 "Capacitor" C0603 92.199,30.55 r180 top
C102 "Capacitor" C0402 88.858,40.002 r0 bottom
C103 "Capacitor" C0402 81.308,31.6 r0 top
C104 "Capacitor" C0402 82.908,31.6 r0 top
C105 "Capacitor" C0402 92.883,38.6 r180 bottom
C106 "Capacitor" C0402 81.932,41.782 r0 bottom
C107 "Capacitor" C0402 92.983,41.2 r0 bottom
C108 "Capacitor" C0402 92.2,31.6 r180 top
C109 "Capacitor" C0603 96.808,48.825 r0 bottom
C110 "Capacitor" C0603 109.05,36.825 r180 top
C111 "Capacitor" C0402 98.094,37.817 r0 top
C112 "Capacitor" C0402 109.408,47.45 r0 bottom
C113 "Capacitor" C0402 106.133,46.17 r180 bottom
C114 "Capacitor" C0402 99.708,37.825 r0 top
C115 "Capacitor" C0402 109.05,37.825 r180 top
C116 "Capacitor" C0402 98.308,47.8 r0 bottom
C117 "Capacitor" C0402 78.025,59.864 r0 bottom
C118 "Capacitor" C0402 75.26,57.43 r90 bottom
C119 "Capacitor" C0402 107.783,46.17 r0 bottom
C120 "Capacitor" C0402 101.358,37.825 r180 top
C121 "Capacitor" C0402 104.333,46.36 r180 bottom
C122 "Capacitor" C0402 112.025,43.715 r180 bottom
C123 "Capacitor" C0603 108.132,51.058 r270 bottom
C124 "Capacitor" C0603 109.133,36.775 r90 bottom
C125 "Capacitor" C0402 112.033,45.525 r180 bottom
C126 "Capacitor" C0402 98.283,34.825 r90 bottom
C127 "Capacitor" C0402 100.208,34.825 r90 bottom
C128 "Capacitor" C0402 82.015,56.705 r90 bottom
C129 "Capacitor" C0402 104.758,51.3 r270 bottom
C130 "Capacitor" C0402 77.027,55.055 r270 bottom
C131 "Capacitor" C0402 102.833,51.3 r270 bottom
C132 "Capacitor" C0402 99.058,51.3 r270 bottom
C133 "Capacitor" C0402 100.908,51.3 r270 bottom
C134 "Capacitor" C0402 107.608,36.375 r90 bottom
C135 "Capacitor" C0402 105.833,36.35 r90 bottom
C136 "Capacitor" C0402 112.033,41.875 r180 bottom
C137 "Capacitor" C0402 85.457,31.6 r180 top
C138 "Capacitor" C0402 87.658,40.75 r90 bottom
C139 "Capacitor" C0402 102.108,34.825 r90 bottom
C140 "Capacitor" C0402 104.008,34.825 r90 bottom
C146 "Capacitor" C0402 77.733,31.4 r180 top
C147 "Cap_POL_TANA" CPOL_TCJ-B_1210_H210 9.311,40.906 r180 top
C148 "Capacitor" C0402 76.11,55.855 r270 bottom
C151 "Capacitor" C0201_MURATA_GRM033_H0P3 66.446,35.716 r0 bottom
C167 "Capacitor" C0402 111.183,36.35 r180 top
C177 "Capacitor" C0402 112.475,49.305 r180 top
C183 "Capacitor" C0603 35.95,53.075 r270 top
C184 "Capacitor" C0603 34.997,42.625 r180 top
C185 "Capacitor" C0805 40.1,40.25 r270 top
C186 "Capacitor" C0805 41.9,40.25 r270 top
C187 "Capacitor" C0805 38.3,40.25 r270 top
C188 "Capacitor" C0402 34.025,37.04 r90 top
C189 "Capacitor" C0402 33.2,37.04 r90 top
C190 "Capacitor" C0402 35.25,37.515 r270 top
C192 "Capacitor" C0201_MURATA_GRM033_H0P3 56.8,45.825 r90 bottom
C193 "Capacitor" C0805 24.3,53.8 r270 top
C194 "Capacitor" C0805 28,53.8 r270 top
C195 "Capacitor" C0201_MURATA_GRM033_H0P3 62.675,46.787 r180 bottom
C196 "Capacitor" C0201_MURATA_GRM033_H0P3 60.8,45.85 r0 bottom
C197 "Capacitor" C0201_MURATA_GRM033_H0P3 58.625,45.425 r0 bottom
C198 "Capacitor" C0805 26.15,53.8 r270 top
C199 "Capacitor" C0603 22.175,42.6 r90 top
C200 "Capacitor" C0603 15.275,45.05 r0 top
C201 "Capacitor" C0201_MURATA_GRM033_H0P3 57.375,45.825 r90 bottom
C202 "Capacitor" C0603 15.275,42.45 r0 top
C203 "Capacitor" C0805 19,39.173 r270 top
C204 "Capacitor" C0805 17.2,39.173 r270 top
C205 "Capacitor" C0201_MURATA_GRM033_H0P3 60.177,46.829 r0 bottom
C206 "Capacitor" C0805 13.6,39.173 r270 top
C207 "Capacitor" C0805 15.4,39.173 r270 top
C208 "Capacitor" C0402 29.675,35.13 r270 top
C209 "Capacitor" C0402 30.35,36.87 r90 top
C213 "Capacitor" C0402 28.175,37.72 r90 top
C214 "Capacitor" C0402 27.6,35.75 r270 top
C215 "Capacitor" C0402 26.775,36.06 r270 top
C216 "Capacitor" C0402 25.5,36.725 r90 top
C217 "Capacitor" C0402 24.725,37.87 r270 top
C219 "Capacitor" C0402 24.727,35.695 r90 top
C220 "Capacitor" C0201_MURATA_GRM033_H0P3 59.609,44.131 r90 bottom
C225 "Capacitor" C0201_H0P5 59.425,40.6 r90 bottom
C234 "Capacitor" C0201_MURATA_GRM033_H0P3 56.064,38.473 r90 bottom
C235 "Capacitor" C0201_H0P5 58.575,35.625 r0 bottom
C236 "Capacitor" C0201_MURATA_GRM033_H0P3 57.35,44.6 r270 bottom
C237 "Capacitor" C0201_MURATA_GRM033_H0P3 56.696,44.605 r270 bottom
C238 "Capacitor" C0201_MURATA_GRM033_H0P3 65.758,44.894 r0 bottom
C239 "Capacitor" C0201_MURATA_GRM033_H0P3 64.125,46.837 r0 bottom
C240 "Capacitor" C0201_MURATA_GRM033_H0P3 59.05,44.575 r90 bottom
C244 "Capacitor" C0201_MURATA_GRM033_H0P3 58.6,36.331 r0 bottom
C246 "Capacitor" C0201_MURATA_GRM033_H0P3 67.666,34.986 r180 bottom
C248 "Capacitor" C0201_MURATA_GRM033_H0P3 58.958,33.002 r0 top
C250 "Capacitor" C0201_MURATA_GRM033_H0P3 58.958,33.572 r0 top
C251 "Capacitor" C0201_MURATA_GRM033_H0P3 68.165,33.588 r180 bottom
C252 "Capacitor" C0201_MURATA_GRM033_H0P3 66.255,36.575 r90 bottom
C253 "Capacitor" C0201_MURATA_GRM033_H0P3 67.666,34.367 r180 bottom
C260 "Capacitor" C0201_MURATA_GRM033_H0P3 66.473,35.094 r0 bottom
CN12 "" CON_MOLEX_53047-0210 47.8,46.475 r180 bottom
D6 "DIODE_3P_DUAL_COMMON_CATHODE" DIO_SOT23 48.773,41.573 r90 bottom
D7 "BAT60JFILM" DIO_SOD323 79.125,61.563 r180 bottom
L1 "Inductor" IND_2016_MURATA_LQM2MPN2R2NG0 26.795,51.175 r180 top
L2 "Inductor" IND_2520_TOKO_DFE252012P 34.915,50.45 r0 top
L3 "Inductor" IND_2016_MURATA_LQM2MPN2R2NG0 21.85,49.075 r90 top
L4 "Inductor" IND_2520_TOKO_DFE252012P 36.425,44.6 r0 top
L5 "Inductor" IND_2016_MURATA_LQM2MPN2R2NG0 19.025,42.7 r180 top
L6 "Inductor" IND_2016_MURATA_LQM2MPN2R2NG0 35.5,40 r0 top
L7 "Inductor" IND_2016_MURATA_LQM2MPN2R2NG0 21.4,38.05 r180 top
LD11 "LED_green" LED_0603_OSRAM_LG-Q396-PS-35_GREEN_1A2K_H0P4 11.386,35.272 r270 top
LNK1 "link_200" LINK200 29.1,52.123 r0 top
LNK2 "link_200" LINK200 44.541,44.7 r90 top
LNK4 "link_200" LINK200 18.85,49.125 r180 top
LNK7 "link_200" LINK200 40.95,43.35 r270 top
LNK8 "link_200" LINK200 16.7,45.498 r0 top
LNK11 "link_200" LINK200 43.1,39.44 r180 top
R1 "Resistor" R0201_H0P23 66.417,43.85 r270 bottom
R11 "Resistor" R0603 67,30.375 r90 bottom
R27 "Resistor" R0402 48.355,38.872 r180 top
R46 "" R0402 31.15,49.998 r270 top
R57 "" R0402 31.85,35.95 r90 top
R59 "" R0402 21.48,35.695 r90 top
R60 "" R0402 22.53,35.695 r90 top
R61 "" R0402 23.58,35.695 r90 top
R64 "" R0402 53.485,37.575 r180 top
R66 "Resistor" R0402 48.633,43.917 r180 bottom
R67 "Resistor" R0402 46.3,40.125 r270 bottom
R75 "" R0402 55.959,33.546 r0 top
R81 "" R0402 31.163,52.348 r270 top
R101 "Resistor" R0402 74.375,56.325 r90 bottom
R103 "Resistor" R0402 80.171,57.511 r90 bottom
R104 "Resistor" R0402 80.175,55.805 r270 bottom
R116 "Resistor" R0402 104.233,49.475 r90 bottom
R117 "Resistor" R0402 105.408,38.35 r270 bottom
R118 "Resistor" R0402 102.333,49.475 r90 bottom
R119 "Resistor" R0402 103.283,49.475 r90 bottom
R120 "Resistor" R0402 99.708,36.825 r270 bottom
R121 "Resistor" R0402 101.383,49.475 r90 bottom
R122 "Resistor" R0402 98.758,36.825 r270 bottom
R123 "Resistor" R0402 98.533,49.475 r90 bottom
R124 "Resistor" R0402 97.808,36.825 r270 bottom
R125 "Resistor" R0402 100.433,49.475 r90 bottom
R126 "Resistor" R0402 104.458,38.35 r270 bottom
R127 "Resistor" R0402 103.508,36.825 r270 bottom
R128 "Resistor" R0402 106.358,38.35 r270 bottom
R129 "Resistor" R0402 99.483,49.475 r90 bottom
R130 "Resistor" R0402 102.558,36.825 r270 bottom
R131 "Resistor" R0402 107.308,38.35 r270 bottom
R132 "Resistor" R0402 105.183,49.475 r90 bottom
R133 "Resistor" R0402 100.658,36.825 r270 bottom
R134 "Resistor" R0402 109.983,46 r0 bottom
R135 "Resistor" R0402 109.333,41.25 r0 bottom
R136 "Resistor" R0402 109.983,42.2 r0 bottom
R137 "Resistor" R0402 109.983,44.1 r0 bottom
R138 "Resistor" R0402 101.608,36.825 r270 bottom
R139 "Resistor" R0402 109.983,43.15 r0 bottom
R140 "Resistor" R0402 109.983,45.05 r0 bottom
R141 "Resistor" R0402 89.933,41.85 r270 bottom
R142 "Resistor" R0402 88.975,41.8 r90 bottom
R143 "Resistor" R0402 84.183,31.175 r90 top
R144 "Resistor" R0402 82.908,30.75 r0 top
R145 "Resistor" R0402 86.73,31.175 r90 top
R146 "Resistor" R0402 105.558,47.735 r0 bottom
R147 "Resistor" R0402 106.532,48.685 r180 bottom
R148 "Resistor" R0402 100.674,36.946 r180 top
R149 "Resistor" R0402 100.158,36 r0 top
R150 "Resistor" R0402 104.6,37.725 r180 top
R156 "Resistor" R0402 95.033,47.475 r270 bottom
R167 "Resistor" R0402 104.533,41.425 r90 bottom
R210 "Resistor" R0402 11.386,37.465 r270 top
R248 "Resistor" R0402 80.657,58.98 r0 bottom
R260 "Resistor" R0402 28.805,50.13 r270 bottom
R261 "Resistor" R0402 29.78,50.13 r270 bottom
R267 "" R0402 57.773,34.723 r180 bottom
R269 "" R0402 58.956,31.808 r90 top
R272 "Resistor" R0402 21.95,33.879 r0 bottom
R286 "" R0402 67.89,32.365 r90 bottom
TP21 "Test Point" TP_SMD_1MM 78.516,55.665 r90 bottom
U1 "STM32MP257FAK3" ICC_TFBGA424_14X14_P050_H1P20_CODE-B0A2 62.875,41.325 r0 top locked
U2 "NT5CC256M16ER-EK" ICC_VFBGA96_9x13_P080 87.657,36.775 r270 top
U8 "NT5CC256M16ER-EK" ICC_VFBGA96_9x13_P080 104.132,43 r270 top
U26 "STPMIC25APQR" ICC_QFN56-EPAD_6P5X6P5_P040 28.5,43.8 r90 top
U37 "eMMC_THGBMTG5D1LBAIL" ICC_P-WFBGA153_13X11P5_P050 77.675,58.405 r0 top
X1 "XTAL_2_PINS" CRY_NX2012SA_2P 51.059,37.225 r270 top
X2 "XTAL_4_PINS" CRY_NX1612SA_4P 54.759,32.135 r180 top

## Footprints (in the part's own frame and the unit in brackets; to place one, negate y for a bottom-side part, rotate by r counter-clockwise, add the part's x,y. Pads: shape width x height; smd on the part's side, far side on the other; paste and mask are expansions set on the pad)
C0201_H0P5 [mm] "MCD-01534"
  rect 0.4x0.5 smd mask+0: 1(-0.3,0) 2(0.3,0)
C0201_MURATA_GRM033_H0P3 [mm] "GRM033R60J105ME11"
  rect 0.35x0.35 smd mask+0: 1(-0.275,0) 2(0.275,0)
C0402 [mm]
  rect 0.51x0.56 smd mask+0: 1(-0.45,0) 2(0.45,0)
C0603 [mm]
  rect 0.64x0.89 smd mask+0: 1(-0.7,0) 2(0.7,0)
  silkscreen extent -1.05,-0.55 1.02,0.55
C0805 [mm]
  rect 0.9x1.4 smd mask+0: 1(-0.85,0) 2(0.85,0)
  silkscreen extent -1.3,-0.77 1.3,0.77
CON_MOLEX_53047-0210 [mm]
  oval 1x1.3 hole 0.5 mask+0: 1(-0.625,0) 2(0.625,0)
  silkscreen extent -2.12,-1.15 2.13,2.05
CPOL_TCJ-B_1210_H210 [mm] "MCD-01791"
  rect 1.35x2.8 smd mask+0: 1(-1.375,0) 2(1.375,0)
  silkscreen extent -2.33,-1.68 1.85,1.68
CRY_NX1612SA_4P [mm] "MCD-02262"
  rect 0.75x0.6 smd mask+0: 1(-0.525,-0.375) 2(0.525,-0.375) 3(0.525,0.375) 4(-0.525,0.375)
  silkscreen extent -1.02,-0.8 0.03,0.6
CRY_NX2012SA_2P [mm]
  rect 1x1.25 smd mask+0: 1(-0.75,0) 2(0.75,0)
  silkscreen extent -1.05,-0.75 1.05,0.75
DIO_SOD323 [mm]
  rect 1.06x0.54 smd mask+0: 1(-1.07,0) 2(1.07,0)
  silkscreen extent -0.9,-0.72 0.9,0.72
DIO_SOT23 [mm]
  rect 1x1.4 smd mask+0: 1(-0.95,-1.1) 2(0.95,-1.1) 3(0,1.1)
  silkscreen extent -1.63,-0.82 1.63,0.82
ICC_P-WFBGA153_13X11P5_P050 [mm]
  round 0.23 smd mask+0: A1(-3.25,-3.25) A2(-3.25,-2.75) A3(-3.25,-2.25) A4(-3.25,-1.75) A5(-3.25,-1.25) A6(-3.25,-0.75) A7(-3.25,-0.25) A8(-3.25,0.25) A9(-3.25,0.75) A10(-3.25,1.25) A11(-3.25,1.75) A12(-3.25,2.25) A13(-3.25,2.75) A14(-3.25,3.25) B1(-2.75,-3.25) B2(-2.75,-2.75) B3(-2.75,-2.25) B4(-2.75,-1.75) B5(-2.75,-1.25) B6(-2.75,-0.75) B7(-2.75,-0.25) B8(-2.75,0.25) B9(-2.75,0.75) B10(-2.75,1.25) B11(-2.75,1.75) B12(-2.75,2.25) B13(-2.75,2.75) B14(-2.75,3.25) C1(-2.25,-3.25) C2(-2.25,-2.75) C3(-2.25,-2.25) C4(-2.25,-1.75) C5(-2.25,-1.25) C6(-2.25,-0.75) C7(-2.25,-0.25) C8(-2.25,0.25) C9(-2.25,0.75) C10(-2.25,1.25) C11(-2.25,1.75) C12(-2.25,2.25) C13(-2.25,2.75) C14(-2.25,3.25) D1(-1.75,-3.25) D2(-1.75,-2.75) D3(-1.75,-2.25) D4(-1.75,-1.75) D12(-1.75,2.25) D13(-1.75,2.75) D14(-1.75,3.25) E1(-1.25,-3.25) E2(-1.25,-2.75) E3(-1.25,-2.25) E5(-1.25,-1.25) E6(-1.25,-0.75) E7(-1.25,-0.25) E8(-1.25,0.25) E9(-1.25,0.75) E10(-1.25,1.25) E12(-1.25,2.25) E13(-1.25,2.75) E14(-1.25,3.25) F1(-0.75,-3.25) F2(-0.75,-2.75) F3(-0.75,-2.25) F5(-0.75,-1.25) F10(-0.75,1.25) F12(-0.75,2.25) F13(-0.75,2.75) F14(-0.75,3.25) G1(-0.25,-3.25) G2(-0.25,-2.75) G3(-0.25,-2.25) G5(-0.25,-1.25) G10(-0.25,1.25) G12(-0.25,2.25) G13(-0.25,2.75) G14(-0.25,3.25) H1(0.25,-3.25) H2(0.25,-2.75) H3(0.25,-2.25) H5(0.25,-1.25) H10(0.25,1.25) H12(0.25,2.25) H13(0.25,2.75) H14(0.25,3.25) J1(0.75,-3.25) J2(0.75,-2.75) J3(0.75,-2.25) J5(0.75,-1.25) J10(0.75,1.25) J12(0.75,2.25) J13(0.75,2.75) J14(0.75,3.25) K1(1.25,-3.25) K2(1.25,-2.75) K3(1.25,-2.25) K5(1.25,-1.25) K6(1.25,-0.75) K7(1.25,-0.25) K8(1.25,0.25) K9(1.25,0.75) K10(1.25,1.25) K12(1.25,2.25) K13(1.25,2.75) K14(1.25,3.25) L1(1.75,-3.25) L2(1.75,-2.75) L3(1.75,-2.25) L12(1.75,2.25) L13(1.75,2.75) L14(1.75,3.25) M1(2.25,-3.25) M2(2.25,-2.75) M3(2.25,-2.25) M4(2.25,-1.75) M5(2.25,-1.25) M6(2.25,-0.75) M7(2.25,-0.25) M8(2.25,0.25) M9(2.25,0.75) M10(2.25,1.25) M11(2.25,1.75) M12(2.25,2.25) M13(2.25,2.75) M14(2.25,3.25) N1(2.75,-3.25) N2(2.75,-2.75) N3(2.75,-2.25) N4(2.75,-1.75) N5(2.75,-1.25) N6(2.75,-0.75) N7(2.75,-0.25) N8(2.75,0.25) N9(2.75,0.75) N10(2.75,1.25) N11(2.75,1.75) N12(2.75,2.25) N13(2.75,2.75) N14(2.75,3.25) P1(3.25,-3.25) P2(3.25,-2.75) P3(3.25,-2.25) P4(3.25,-1.75) P5(3.25,-1.25) P6(3.25,-0.75) P7(3.25,-0.25) P8(3.25,0.25) P9(3.25,0.75) P10(3.25,1.25) P11(3.25,1.75) P12(3.25,2.25) P13(3.25,2.75) P14(3.25,3.25)
  silkscreen extent -6.78,-6.02 6.63,5.87
ICC_QFN56-EPAD_6P5X6P5_P040 [mm] "MCD-03000"
  rect 0.55x0.21 smd mask+0: 1(-3.245,2.6) 14(-3.245,-2.6) 29(3.245,-2.6) 42(3.245,2.6)
  rect 0.7x0.21 smd mask+0: 2(-3.17,2.2) 3(-3.17,1.8) 4(-3.17,1.4) 5(-3.17,1) 6(-3.17,0.6) 7(-3.17,0.2) 8(-3.17,-0.2) 9(-3.17,-0.6) 10(-3.17,-1) 11(-3.17,-1.4) 12(-3.17,-1.8) 13(-3.17,-2.2) 30(3.17,-2.2) 31(3.17,-1.8) 32(3.17,-1.4) 33(3.17,-1) 34(3.17,-0.6) 35(3.17,-0.2) 36(3.17,0.2) 37(3.17,0.6) 38(3.17,1) 39(3.17,1.4) 40(3.17,1.8) 41(3.17,2.2)
  rect 0.21x0.55 smd mask+0: 15(-2.6,-3.245) 28(2.6,-3.245) 43(2.6,3.245) 56(-2.6,3.245)
  rect 0.21x0.7 smd mask+0: 16(-2.2,-3.17) 17(-1.8,-3.17) 18(-1.4,-3.17) 19(-1,-3.17) 20(-0.6,-3.17) 21(-0.2,-3.17) 22(0.2,-3.17) 23(0.6,-3.17) 24(1,-3.17) 25(1.4,-3.17) 26(1.8,-3.17) 27(2.2,-3.17) 44(2.2,3.17) 45(1.8,3.17) 46(1.4,3.17) 47(1,3.17) 48(0.6,3.17) 49(0.2,3.17) 50(-0.2,3.17) 51(-0.6,3.17) 52(-1,3.17) 53(-1.4,3.17) 54(-1.8,3.17) 55(-2.2,3.17)
  rect 4.7x4.7 smd mask+0: 57(0,0)
  silkscreen extent -3.44,3 -3.01,3.42
ICC_TFBGA424_14X14_P050_H1P20_CODE-B0A2 [mm] "MCD_03375"
  round 0.23 smd paste+0.025 mask+0: 1A1(-2.75,2.75) 1A3(-1.75,2.75) 1A5(-0.75,2.75) 1A7(0.25,2.75) 1A9(1.25,2.75) 1A11(2.25,2.75) 1B2(-2.25,2.25) 1B4(-1.25,2.25) 1B6(-0.25,2.25) 1B8(0.75,2.25) 1B10(1.75,2.25) 1B12(2.75,2.25) 1C1(-2.75,1.75) 1C3(-1.75,1.75) 1C5(-0.75,1.75) 1C7(0.25,1.75) 1C9(1.25,1.75) 1C11(2.25,1.75) 1D2(-2.25,1.25) 1D4(-1.25,1.25) 1D6(-0.25,1.25) 1D8(0.75,1.25) 1D10(1.75,1.25) 1D12(2.75,1.25) 1E1(-2.75,0.75) 1E3(-1.75,0.75) 1E5(-0.75,0.75) 1E7(0.25,0.75) 1E9(1.25,0.75) 1E11(2.25,0.75) 1F2(-2.25,0.25) 1F4(-1.25,0.25) 1F6(-0.25,0.25) 1F8(0.75,0.25) 1F10(1.75,0.25) 1F12(2.75,0.25) 1G1(-2.75,-0.25) 1G3(-1.75,-0.25) 1G5(-0.75,-0.25) 1G7(0.25,-0.25) 1G9(1.25,-0.25) 1G11(2.25,-0.25) 1H2(-2.25,-0.75) 1H4(-1.25,-0.75) 1H6(-0.25,-0.75) 1H8(0.75,-0.75) 1H10(1.75,-0.75) 1H12(2.75,-0.75) 1J1(-2.75,-1.25) 1J3(-1.75,-1.25) 1J5(-0.75,-1.25) 1J7(0.25,-1.25) 1J9(1.25,-1.25) 1J11(2.25,-1.25) 1K2(-2.25,-1.75) 1K4(-1.25,-1.75) 1K6(-0.25,-1.75) 1K8(0.75,-1.75) 1K10(1.75,-1.75) 1K12(2.75,-1.75) 1L1(-2.75,-2.25) 1L3(-1.75,-2.25) 1L5(-0.75,-2.25) 1L7(0.25,-2.25) 1L9(1.25,-2.25) 1L11(2.25,-2.25) 1M2(-2.25,-2.75) 1M4(-1.25,-2.75) 1M6(-0.25,-2.75) 1M8(0.75,-2.75) 1M10(1.75,-2.75) 1M12(2.75,-2.75) A1(-6.5,6.5) A2(-6,6.5) A3(-5.5,6.5) A6(-4,6.5) A7(-3.5,6.5) A10(-2,6.5) A11(-1.5,6.5) A14(0,6.5) A15(0.5,6.5) A18(2,6.5) A19(2.5,6.5) A22(4,6.5) A23(4.5,6.5) A26(6,6.5) A27(6.5,6.5) AA1(-6.5,-3.5) AA2(-6,-3.5) AA3(-5.5,-3.5) AA5(-4.5,-3.5) AA7(-3.5,-3.5) AA9(-2.5,-3.5) AA11(-1.5,-3.5) AA13(-0.5,-3.5) AA15(0.5,-3.5) AA17(1.5,-3.5) AA19(2.5,-3.5) AA21(3.5,-3.5) AA23(4.5,-3.5) AA25(5.5,-3.5) AA26(6,-3.5) AB1(-6.5,-4) AB2(-6,-4) AB3(-5.5,-4) AB4(-5,-4) AB6(-4,-4) AB8(-3,-4) AB10(-2,-4) AB12(-1,-4) AB14(0,-4) AB16(1,-4) AB18(2,-4) AB20(3,-4) AB22(4,-4) AB24(5,-4) AB25(5.5,-4) AB26(6,-4) AB27(6.5,-4) AC2(-6,-4.5) AC3(-5.5,-4.5) AC5(-4.5,-4.5) AC7(-3.5,-4.5) AC9(-2.5,-4.5) AC11(-1.5,-4.5) AC13(-0.5,-4.5) AC15(0.5,-4.5) AC17(1.5,-4.5) AC19(2.5,-4.5) AC21(3.5,-4.5) AC23(4.5,-4.5) AC25(5.5,-4.5) AC26(6,-4.5) AC27(6.5,-4.5) AD3(-5.5,-5) AD4(-5,-5) AD6(-4,-5) AD8(-3,-5) AD10(-2,-5) AD12(-1,-5) AD14(0,-5) AD16(1,-5) AD18(2,-5) AD20(3,-5) AD22(4,-5) AD24(5,-5) AD25(5.5,-5) AE1(-6.5,-5.5) AE2(-6,-5.5) AE3(-5.5,-5.5) AE4(-5,-5.5) AE5(-4.5,-5.5) AE6(-4,-5.5) AE7(-3.5,-5.5) AE8(-3,-5.5) AE9(-2.5,-5.5) AE10(-2,-5.5) AE11(-1.5,-5.5) AE12(-1,-5.5) AE13(-0.5,-5.5) AE14(0,-5.5) AE15(0.5,-5.5) AE16(1,-5.5) AE17(1.5,-5.5) AE18(2,-5.5) AE19(2.5,-5.5) AE20(3,-5.5) AE21(3.5,-5.5) AE22(4,-5.5) AE23(4.5,-5.5) AE24(5,-5.5) AE25(5.5,-5.5) AE26(6,-5.5) AF1(-6.5,-6) AF2(-6,-6) AF3(-5.5,-6) AF5(-4.5,-6) AF6(-4,-6) AF7(-3.5,-6) AF9(-2.5,-6) AF10(-2,-6) AF11(-1.5,-6) AF13(-0.5,-6) AF14(0,-6) AF15(0.5,-6) AF17(1.5,-6) AF18(2,-6) AF19(2.5,-6) AF21(3.5,-6) AF22(4,-6) AF23(4.5,-6) AF25(5.5,-6) AF26(6,-6) AF27(6.5,-6) AG1(-6.5,-6.5) AG2(-6,-6.5) AG5(-4.5,-6.5) AG6(-4,-6.5) AG9(-2.5,-6.5) AG10(-2,-6.5) AG13(-0.5,-6.5) AG14(0,-6.5) AG17(1.5,-6.5) AG18(2,-6.5) AG21(3.5,-6.5) AG22(4,-6.5) AG25(5.5,-6.5) AG26(6,-6.5) AG27(6.5,-6.5) B1(-6.5,6) B2(-6,6) B3(-5.5,6) B5(-4.5,6) B6(-4,6) B7(-3.5,6) B9(-2.5,6) B10(-2,6) B11(-1.5,6) B13(-0.5,6) B14(0,6) B15(0.5,6) B17(1.5,6) B18(2,6) B19(2.5,6) B21(3.5,6) B22(4,6) B23(4.5,6) B25(5.5,6) B26(6,6) B27(6.5,6) C2(-6,5.5) C3(-5.5,5.5) C4(-5,5.5) C5(-4.5,5.5) C6(-4,5.5) C7(-3.5,5.5) C8(-3,5.5) C9(-2.5,5.5) C10(-2,5.5) C11(-1.5,5.5) C12(-1,5.5) C13(-0.5,5.5) C14(0,5.5) C15(0.5,5.5) C16(1,5.5) C17(1.5,5.5) C18(2,5.5) C19(2.5,5.5) C20(3,5.5) C21(3.5,5.5) C22(4,5.5) C23(4.5,5.5) C24(5,5.5) C25(5.5,5.5) C26(6,5.5) C27(6.5,5.5) D3(-5.5,5) D4(-5,5) D6(-4,5) D8(-3,5) D10(-2,5) D12(-1,5) D14(0,5) D16(1,5) D18(2,5) D20(3,5) D22(4,5) D24(5,5) D25(5.5,5) E1(-6.5,4.5) E2(-6,4.5) E3(-5.5,4.5) E5(-4.5,4.5) E7(-3.5,4.5) E9(-2.5,4.5) E11(-1.5,4.5) E13(-0.5,4.5) E15(0.5,4.5) E17(1.5,4.5) E19(2.5,4.5) E21(3.5,4.5) E23(4.5,4.5) E25(5.5,4.5) E26(6,4.5) F1(-6.5,4) F2(-6,4) F3(-5.5,4) F4(-5,4) F6(-4,4) F8(-3,4) F10(-2,4) F12(-1,4) F14(0,4) F16(1,4) F18(2,4) F20(3,4) F22(4,4) F24(5,4) F25(5.5,4) F26(6,4) F27(6.5,4) G2(-6,3.5) G3(-5.5,3.5) G5(-4.5,3.5) G7(-3.5,3.5) G9(-2.5,3.5) G11(-1.5,3.5) G13(-0.5,3.5) G15(0.5,3.5) G17(1.5,3.5) G19(2.5,3.5) G21(3.5,3.5) G23(4.5,3.5) G25(5.5,3.5) G26(6,3.5) G27(6.5,3.5) H3(-5.5,3) H4(-5,3) H6(-4,3) H22(4,3) H24(5,3) H25(5.5,3) J1(-6.5,2.5) J2(-6,2.5) J3(-5.5,2.5) J5(-4.5,2.5) J7(-3.5,2.5) J21(3.5,2.5) J23(4.5,2.5) J25(5.5,2.5) J26(6,2.5) K1(-6.5,2) K2(-6,2) K3(-5.5,2) K4(-5,2) K6(-4,2) K22(4,2) K24(5,2) K25(5.5,2) K26(6,2) K27(6.5,2) L2(-6,1.5) L3(-5.5,1.5) L5(-4.5,1.5) L7(-3.5,1.5) L21(3.5,1.5) L23(4.5,1.5) L25(5.5,1.5) L26(6,1.5) L27(6.5,1.5) M3(-5.5,1) M4(-5,1) M6(-4,1) M22(4,1) M24(5,1) M25(5.5,1) N1(-6.5,0.5) N2(-6,0.5) N3(-5.5,0.5) N5(-4.5,0.5) N7(-3.5,0.5) N21(3.5,0.5) N23(4.5,0.5) N25(5.5,0.5) N26(6,0.5) P1(-6.5,0) P2(-6,0) P3(-5.5,0) P4(-5,0) P6(-4,0) P22(4,0) P24(5,0) P25(5.5,0) P26(6,0) P27(6.5,0) R2(-6,-0.5) R3(-5.5,-0.5) R5(-4.5,-0.5) R7(-3.5,-0.5) R21(3.5,-0.5) R23(4.5,-0.5) R25(5.5,-0.5) R26(6,-0.5) R27(6.5,-0.5) T3(-5.5,-1) T4(-5,-1) T6(-4,-1) T22(4,-1) T24(5,-1) T25(5.5,-1) U1(-6.5,-1.5) U2(-6,-1.5) U3(-5.5,-1.5) U5(-4.5,-1.5) U7(-3.5,-1.5) U21(3.5,-1.5) U23(4.5,-1.5) U25(5.5,-1.5) U26(6,-1.5) V1(-6.5,-2) V2(-6,-2) V3(-5.5,-2) V4(-5,-2) V6(-4,-2) V22(4,-2) V24(5,-2) V25(5.5,-2) V26(6,-2) V27(6.5,-2) W2(-6,-2.5) W3(-5.5,-2.5) W5(-4.5,-2.5) W7(-3.5,-2.5) W21(3.5,-2.5) W23(4.5,-2.5) W25(5.5,-2.5) W26(6,-2.5) W27(6.5,-2.5) Y3(-5.5,-3) Y4(-5,-3) Y6(-4,-3) Y22(4,-3) Y24(5,-3) Y25(5.5,-3)
  silkscreen extent -7.17,-7 7,7.17
ICC_VFBGA96_9x13_P080 [mm]
  round 0.4 smd mask+0: A1(-3.2,6) A2(-2.4,6) A3(-1.6,6) A7(1.6,6) A8(2.4,6) A9(3.2,6) B1(-3.2,5.2) B2(-2.4,5.2) B3(-1.6,5.2) B7(1.6,5.2) B8(2.4,5.2) B9(3.2,5.2) C1(-3.2,4.4) C2(-2.4,4.4) C3(-1.6,4.4) C7(1.6,4.4) C8(2.4,4.4) C9(3.2,4.4) D1(-3.2,3.6) D2(-2.4,3.6) D3(-1.6,3.6) D7(1.6,3.6) D8(2.4,3.6) D9(3.2,3.6) E1(-3.2,2.8) E2(-2.4,2.8) E3(-1.6,2.8) E7(1.6,2.8) E8(2.4,2.8) E9(3.2,2.8) F1(-3.2,2) F2(-2.4,2) F3(-1.6,2) F7(1.6,2) F8(2.4,2) F9(3.2,2) G1(-3.2,1.2) G2(-2.4,1.2) G3(-1.6,1.2) G7(1.6,1.2) G8(2.4,1.2) G9(3.2,1.2) H1(-3.2,0.4) H2(-2.4,0.4) H3(-1.6,0.4) H7(1.6,0.4) H8(2.4,0.4) H9(3.2,0.4) J1(-3.2,-0.4) J2(-2.4,-0.4) J3(-1.6,-0.4) J7(1.6,-0.4) J8(2.4,-0.4) J9(3.2,-0.4) K1(-3.2,-1.2) K2(-2.4,-1.2) K3(-1.6,-1.2) K7(1.6,-1.2) K8(2.4,-1.2) K9(3.2,-1.2) L1(-3.2,-2) L2(-2.4,-2) L3(-1.6,-2) L7(1.6,-2) L8(2.4,-2) L9(3.2,-2) M1(-3.2,-2.8) M2(-2.4,-2.8) M3(-1.6,-2.8) M7(1.6,-2.8) M8(2.4,-2.8) M9(3.2,-2.8) N1(-3.2,-3.6) N2(-2.4,-3.6) N3(-1.6,-3.6) N7(1.6,-3.6) N8(2.4,-3.6) N9(3.2,-3.6) P1(-3.2,-4.4) P2(-2.4,-4.4) P3(-1.6,-4.4) P7(1.6,-4.4) P8(2.4,-4.4) P9(3.2,-4.4) R1(-3.2,-5.2) R2(-2.4,-5.2) R3(-1.6,-5.2) R7(1.6,-5.2) R8(2.4,-5.2) R9(3.2,-5.2) T1(-3.2,-6) T2(-2.4,-6) T3(-1.6,-6) T7(1.6,-6) T8(2.4,-6) T9(3.2,-6)
  silkscreen extent -4.72,-6.55 4.55,6.73
IND_2016_MURATA_LQM2MPN2R2NG0 [mm]
  rect 0.8x1.8 smd mask+0: 1(-0.8,0) 2(0.8,0)
  silkscreen extent -0.28,-0.87 0.28,0.87
IND_2520_TOKO_DFE252012P [mm]
  rect 0.8x2 smd mask+0: 1(-1,0) 2(1,0)
  silkscreen extent -1.35,-1.12 1.35,1.12
LED_0603_OSRAM_LG-Q396-PS-35_GREEN_1A2K_H0P4 [mm]
  rect 0.8x0.8 smd mask+0: 1(-0.75,0) 2(0.75,0)
  silkscreen extent -0.85,-0.53 1.28,0.53
LINK200 [mm]
  rect 0.2x0.35 smd paste-10 mask+0: 1(0,-0.225) 2(0,0.225)
R0201_H0P23 [mm] "MCD-00702"
  rect 0.4x0.5 smd mask+0: 1(-0.3,0) 2(0.3,0)
R0402 [mm]
  rect 0.51x0.7 smd mask+0: 1(-0.45,0) 2(0.45,0)
R0603 [mm]
  rect 0.64x1 smd mask+0: 1(-0.7,0) 2(0.7,0)
  silkscreen extent -1.05,-0.58 1.05,0.58
SWI_WE_434121025816 [mm] "MCD-03492"
  rect 1.5x1.4 smd: 1(-3.25,0) 2(3.25,0)
  silkscreen extent -3,-1.95 3,1.95
TP_SMD_1MM [mm]
  round 1 smd paste-10 mask+0: 1(0,0)
  silkscreen extent -0.7,-0.7 0.7,0.7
